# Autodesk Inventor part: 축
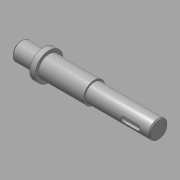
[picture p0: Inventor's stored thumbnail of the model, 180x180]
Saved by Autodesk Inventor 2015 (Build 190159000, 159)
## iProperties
Created: 2015-09
Part Number: 축
Material: 강철, 연강
Document SubType Name: Modeling
Designer: mduedu
Density: 7.86 g/cm^3
Mass: 263.424 g
Surface Area: 86.4309 cm^2
Volume: 33.5145 cm^3
Appearance: 강철
Author: mduedu
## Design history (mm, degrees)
sketch "스케치1"
  geometry: L1 (-64, 0)-(64, 0); L2 (-64, 0)-(-64, 8.5); L3 (-64, 8.5)-(-43, 8.5); L4 (-43, 8.5)-(-43, 13); L5 (-43, 13)-(-38, 13); L6 (-38, 13)-(-38, 10); L7 (-38, 10)-(4, 10); L8 (4, 10)-(4, 8.5); L9 (4, 8.5)-(64, 8.5); L10 (64, 8.5)-(64, 0); 2 further points
  constraints: 20 end point, 5 parallel, 2 horizontal, 2 perpendicular, 1 coincident, 1 midpoint, 1 vertical
  dimensions: "d0" = 128 distance of L1.start L1.end; "d2" = 5 distance of L4.end L5.end; "d3" = 42 distance of L6.end L7.end; "d4" = 60 distance of L8.end L9.end; "d5" = 17 diameter of L3 L1; "d6" = 17 diameter of L9 L1; "d7" = 20 diameter of L7 L1; "d8" = 26 diameter of L5 L1
revolve "회전1" sketch "스케치1" stored, may be unused: angle "d9" = 90 deg
node "작업 평면1"
sketch "스케치2"
  geometry: L1 (5.5, 2.5)-(18.5, 2.5); L2 (18.5, -2.5)-(5.5, -2.5); L3 (5.5, 2.5)-(18.5, -2.5); L4 (18.5, 2.5)-(5.5, -2.5); L5 (30, -8.5)-(30, 8.5) reference; A1 r 2.5 centre (5.5, 0) between (5.5, 2.5) and (5.5, -2.5); A2 r 2.5 centre (18.5, 0) between (18.5, -2.5) and (18.5, 2.5); 2 further points
  constraints: 8 end point, 4 point on circle, 4 tangent, 2 centre point, 2 midpoint, 1 horizontal, 1 horizontal alignment, 1 parallel
  dimensions: "d10" = 18 dimension on A2 A1; "d12" = 9 distance edge to line of A2 L5; "d13" = 5 distance between parallel lines of L2 L1
extrude "돌출1" cut sketch "스케치2" distance "d14" = 3; taper "d15" = 0 deg
node "작업 평면2"
sketch "스케치4"
  geometry: L1 (7, -3)-(-9, -3); L2 (-9, 3)-(7, 3); L3 (-21, 10)-(-21, -10) reference; A1 r 3 centre (-9, 0) between (-9, 3) and (-9, -3); A2 r 3 centre (7, 0) between (7, -3) and (7, 3); 1 further point
  constraints: 4 end point, 4 point on circle, 4 tangent, 2 centre point, 1 horizontal, 1 horizontal alignment, 1 parallel
  dimensions: "d16" = 22 dimension on A1 A2; "d18" = 6 distance between parallel lines of L2 L1; "d19" = 9 distance edge to line of A1 L3
extrude "돌출2" cut sketch "스케치4" distance "d20" = 3.5; taper "d21" = 0 deg
sketch "스케치5"
  geometry: L1 (4, 8.5)-(64, 8.5) reference; L2 (4, -8.5)-(64, -8.5) reference; L3 (37, 8.5)-(37, -8.5); L4 (37, -6.5)-(35, -8.5); L5 (37, -8.5)-(35, -8.5); L6 (37, -8.5)-(37, -6.5); L7 (4, -10)-(4, 10) reference; 1 further point
  constraints: 8 end point, 4 point on line, 1 collinear, 1 perpendicular
  dimensions: "d22" = 4 diameter of L4.end L3; "d24" = 45 deg angle of L3 L4; "d26" = 33 distance between parallel lines of L3 L7
revolve "회전2" sketch "스케치5" stored, may be unused: angle "d27" = 90 deg
chamfer "모따기1" distance "d28" = 1; stored, may be unused: second distance "d29" = 2, angle "d30" = 45 deg
sketch "스케치6"
  geometry: L1 (37, -6.5)-(35, -8.5) reference; L2 (37, -6.5)-(39, -8.5) reference; 2 further points
  constraints: 1 coincident
node "솔리드1"
